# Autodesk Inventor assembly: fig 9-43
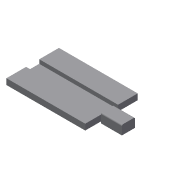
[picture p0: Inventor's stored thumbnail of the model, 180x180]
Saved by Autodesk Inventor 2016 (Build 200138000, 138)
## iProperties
Created: 2013-07
Part Number: fig 9-43
Document SubType Name: Assembly
Designer: CADCIM
Author: CADCIM
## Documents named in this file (3)
- D:\KAVITA\Autodesk Inventor_ 2016 Project_Kavita\Inventor_Part Files\Inventor_2016_Part\c09_Inv_2016\c09_inv_2016_prt\fig 9-43.iam
- D:\KAVITA\Autodesk Inventor_ 2016 Project_Kavita\Inventor_Part Files\Inventor_2016_Part\c09_Inv_2016\c09_inv_2016_prt\15.ipt
- D:\KAVITA\Autodesk Inventor_ 2016 Project_Kavita\Inventor_Part Files\Inventor_2016_Part\c09_Inv_2016\c09_inv_2016_prt\16.ipt
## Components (2 placed, 2 different names)
1. 15:1
2. 16:1
